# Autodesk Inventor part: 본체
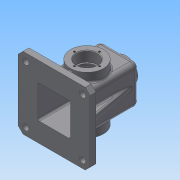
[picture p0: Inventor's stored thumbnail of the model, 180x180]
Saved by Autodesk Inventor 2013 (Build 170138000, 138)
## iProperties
Created: 2018-10
Part Number: 본체
Material: 일반
Document SubType Name: Modeling
Designer: Administrator
Density: 1 g/cm^3
Author: Administrator
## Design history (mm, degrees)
sketch "스케치1"
  geometry: L1 (32.5, -32.5)-(-32.5, -32.5); L2 (-32.5, -32.5)-(-32.5, 32.5); L3 (-32.5, 32.5)-(32.5, 32.5); L4 (32.5, 32.5)-(32.5, -32.5); L5 (32.5, -32.5)-(-32.5, 32.5); L6 (-32.5, -32.5)-(32.5, 32.5); 1 further point
  constraints: 12 end point, 2 midpoint, 2 parallel, 1 horizontal, 1 perpendicular
  dimensions: "d0" = 65 distance of L2.end L3.end; "d1" = 65 distance of L1.end L2.end
extrude "돌출1" new body sketch "스케치1" stored distance "d2" = 110; taper "d3" = 0 deg
sketch "스케치2"
  geometry: L1 (-27.5, 27.5)-(27.5, 27.5); L2 (27.5, 27.5)-(27.5, -27.5); L3 (27.5, -27.5)-(-27.5, -27.5); L4 (-27.5, -27.5)-(-27.5, 27.5); L5 (-27.5, 27.5)-(27.5, -27.5); L6 (27.5, 27.5)-(-27.5, -27.5); 1 further point
  constraints: 12 end point, 2 midpoint, 2 parallel, 1 horizontal, 1 perpendicular
  dimensions: "d4" = 55 distance of L2.end L3.end; "d5" = 55 distance of L1.end L2.end
extrude "돌출2" cut sketch "스케치2" distance "d6" = 105; taper "d7" = 0 deg
fillet "모깎기1" dims "d8" = 8
sketch "스케치3"
  geometry: L1 (57, 0)-(49, 0) reference; C1 r 27.5 at (24.5, 55); 1 further point
  constraints: 1 centre point, 1 coincident
  dimensions: "d9" = 55 diameter of C1; "d10" = 55 distance from line of L1 C1.centre
extrude "돌출3" join sketch "스케치3" distance "d11" = 15; taper "d12" = 0 deg
sketch "스케치4"
  geometry: C1 r 27.5 at (0, 0) reference; 1 further point
  constraints: 1 coincident
hole "구멍1" sketch "스케치4" at (0, 0) diameter "d13" = 30; stored, may be unused: countersink angle "d17" = 90 deg, drill point angle "d19" = 0 deg; dims "d14" = 6, "d15" = 35, "d16" = 17, "d18" = 20
sketch "스케치5"
  geometry: C1 r 17.5 at (0, 0) reference; 1 further point
  constraints: 1 vertical alignment
  dimensions: "d20" = 21 distance of C1.centre point (0, 21)
hole "구멍2" sketch "스케치5" at (0, 21) diameter "d21" = 3.242; stored, may be unused: countersink angle "d25" = 90 deg, drill point angle "d27" = 118 deg; dims "d22" = 8, "d23" = 35, "d24" = 17, "d26" = 10
chamfer "모따기1" distance "d31" = 1; stored, may be unused: second distance "d32" = 2, angle "d33" = 45 deg
fillet "모깎기2" dims "d34" = 0.3
fillet "모깎기3" dims "d35" = 3
chamfer "모따기2" distance "d36" = 1; stored, may be unused: second distance "d37" = 2, angle "d38" = 45 deg
fillet "모깎기4" dims "d39" = 0.3
fillet "모깎기5" dims "d40" = 3
node "작업 평면1"
sketch "스케치6"
  geometry: C1 r 20 at (0, 0); 1 further point
  constraints: 1 centre point, 1 coincident
  dimensions: "d42" = 40 diameter of C1
extrude "돌출4" join sketch "스케치6" stored distance "d43" = 15; taper "d44" = 7 deg
sketch "스케치7"
  geometry: C1 r 20 at (0, 0) reference; 1 further point
  constraints: 1 coincident
hole "구멍3" sketch "스케치7" at (0, 0) diameter "d45" = 22.835; stored, may be unused: countersink angle "d49" = 90 deg, drill point angle "d51" = 118 deg; dims "d46" = 8, "d47" = 35, "d48" = 17, "d50" = 10
chamfer "모따기3" distance "d52" = 1; stored, may be unused: second distance "d53" = 2, angle "d54" = 45 deg
fillet "모깎기6" dims "d55" = 3
fillet "모깎기7" dims "d56" = 3
fillet "모깎기8" dims "d57" = 3
sketch "스케치8"
  geometry: L1 (-24.5, -32.5)-(24.5, -32.5) reference; L2 (32.5, -24.5)-(32.5, 24.5) reference; L3 (24.5, 32.5)-(-24.5, 32.5) reference; L4 (-32.5, 24.5)-(-32.5, -24.5) reference; L5 (60, 60)-(-60, 60); L6 (-60, 60)-(-60, -60); L7 (-60, -60)-(60, -60); L8 (60, -60)-(60, 60); L9 (60, 60)-(-60, -60); L10 (-60, 60)-(60, -60); A1 r 8 centre (24.5, -24.5) between (24.5, -32.5) and (32.5, -24.5) reference; A2 r 8 centre (24.5, 24.5) between (32.5, 24.5) and (24.5, 32.5) reference; A3 r 8 centre (-24.5, 24.5) between (-24.5, 32.5) and (-32.5, 24.5) reference; A4 r 8 centre (-24.5, -24.5) between (-32.5, -24.5) and (-24.5, -32.5) reference; 1 further point
  constraints: 12 end point, 2 midpoint, 2 parallel, 1 horizontal, 1 perpendicular
  dimensions: "d58" = 120 distance of L7.end L6.end; "d59" = 120 distance of L6.end L5.end
extrude "돌출5" join sketch "스케치8" distance "d60" = 10; taper "d61" = 0 deg
chamfer "모따기4" distance "d62" = 8; stored, may be unused: second distance "d63" = 2, angle "d64" = 45 deg
sketch "스케치9"
  geometry: L1 (-47.5, 47.5)-(47.5, 47.5); L2 (47.5, 47.5)-(47.5, -47.5); L3 (47.5, -47.5)-(-47.5, -47.5); L4 (-47.5, -47.5)-(-47.5, 47.5); L5 (-47.5, 47.5)-(47.5, -47.5); L6 (47.5, 47.5)-(-47.5, -47.5); 7 further points
  constraints: 12 end point, 5 coincident, 3 midpoint, 2 parallel, 1 horizontal, 1 perpendicular
  dimensions: "d65" = 95 distance of L2.end L3.end; "d66" = 95 distance of L1.end L2.end
hole "구멍4" sketch "스케치9" at (-47.5, 47.5), (47.5, 47.5), (-47.5, -47.5), (47.5, -47.5) diameter "d67" = 10; stored, may be unused: countersink angle "d71" = 90 deg, drill point angle "d73" = 118 deg; dims "d68" = 8, "d69" = 35, "d70" = 17, "d72" = 10
sketch "스케치10"
  geometry: L1 (-12.418, 65)-(-11.418, 64) reference; L2 (-11.418, 64)-(-11.418, 50) reference; L3 (-11.418, 50)-(-24.5, 50) reference; L4 (-27.5, 47)-(-27.5, -55) reference; L5 (-27.5, -55)-(-60, -55) reference; L6 (-60, -55)-(-60, -45) reference; L7 (-60, -45)-(-32.5, -45) reference; L8 (-32.5, -45)-(-32.5, 47) reference; L9 (-24.5, 55)-(-23.882, 55) reference; L10 (-20.904, 57.634)-(-20, 65) reference; L11 (-20, 65)-(-12.418, 65) reference; L12 (11.418, 64)-(12.418, 65) reference; L13 (12.418, 65)-(20, 65) reference; L14 (20, 65)-(20.904, 57.634) reference; L15 (23.882, 55)-(24.5, 55) reference; L16 (32.5, 47)-(32.5, -45) reference; L17 (32.5, -45)-(60, -45) reference; L18 (60, -45)-(60, -55) reference; L19 (60, -55)-(27.5, -55) reference; L20 (27.5, -55)-(27.5, 47) reference; L21 (24.5, 50)-(11.418, 50) reference; L22 (11.418, 50)-(11.418, 64) reference; L23 (-48, -45)-(-41.054, -5.608); L24 (-48, -45)-(-8, -45); A1 r 3 centre (-24.5, 47) between (-24.5, 50) and (-27.5, 47) reference; A2 r 8 centre (-24.5, 47) between (-24.5, 55) and (-32.5, 47) reference; A3 r 3 centre (-23.882, 58) between (-23.882, 55) and (-20.904, 57.634) reference; A4 r 3 centre (23.882, 58) between (20.904, 57.634) and (23.882, 55) reference; A5 r 8 centre (24.5, 47) between (32.5, 47) and (24.5, 55) reference; A6 r 3 centre (24.5, 47) between (27.5, 47) and (24.5, 50) reference; 1 further point
  constraints: 4 end point, 1 equal length, 1 horizontal, 1 point on line
  dimensions: "d74" = 40 distance of L23.start L23.end; "d75" = 80 deg angle of L24 L23; "d76" = 12 distance of L6.end L23.start
feature "리브1" sketch "스케치10" dims "d77" = 1, "d78" = 10, "d79" = 0, "d80" = 0, "d81" = 1, "d82" = 1
sketch "스케치11"
  geometry: L1 (-21, -36.526)-(-22.621, -37.5) reference; L2 (-22.621, -37.5)-(-22.621, -47.5) reference; L3 (-22.621, -47.5)-(-27.5, -47.5) reference; L4 (-27.5, -47.5)-(-27.5, -35.5) reference; L5 (-30.5, -32.5)-(-45, -32.5) reference; L6 (-45, -32.5)-(-45, -60) reference; L7 (-45, -60)-(-55, -60) reference; L8 (-55, -60)-(-55, -27.5) reference; L9 (-55, -27.5)-(-15, -27.5) reference; L10 (-15, -27.5)-(-15, -30.5) reference; L11 (-15, -30.5)-(-17.2, -30.5) reference; L12 (-17.5, -30.8)-(-17.5, -46.5) reference; L13 (-17.5, -46.5)-(-18.5, -47.5) reference; L14 (-18.5, -47.5)-(-19.379, -47.5) reference; L15 (-19.379, -47.5)-(-19.379, -37.5) reference; L16 (-19.379, -37.5)-(-21, -36.526) reference; L17 (22.621, -37.5)-(21, -36.526) reference; L18 (21, -36.526)-(19.379, -37.5) reference; L19 (19.379, -37.5)-(19.379, -47.5) reference; L20 (19.379, -47.5)-(18.5, -47.5) reference; L21 (18.5, -47.5)-(17.5, -46.5) reference; L22 (17.5, -46.5)-(17.5, -30.8) reference; L23 (17.2, -30.5)-(15, -30.5) reference; L24 (15, -30.5)-(15, -27.5) reference; L25 (15, -27.5)-(47, -27.5) reference; L26 (50, -24.5)-(50, -11.418) reference; L27 (50, -11.418)-(64, -11.418) reference; L28 (64, -11.418)-(65, -12.418) reference; L29 (65, -12.418)-(65, -20) reference; L30 (65, -20)-(57.634, -20.904) reference; L31 (55, -23.882)-(55, -24.5) reference; L32 (47, -32.5)-(30.5, -32.5) reference; L33 (27.5, -35.5)-(27.5, -47.5) reference; L34 (27.5, -47.5)-(22.621, -47.5) reference; L35 (22.621, -47.5)-(22.621, -37.5) reference; L36 (-22.621, 37.5)-(-21, 36.526) reference; L37 (-21, 36.526)-(-19.379, 37.5) reference; L38 (-19.379, 37.5)-(-19.379, 47.5) reference; L39 (-19.379, 47.5)-(-18.5, 47.5) reference; L40 (-18.5, 47.5)-(-17.5, 46.5) reference; L41 (-17.5, 46.5)-(-17.5, 30.8) reference; L42 (-17.2, 30.5)-(-15, 30.5) reference; L43 (-15, 30.5)-(-15, 27.5) reference; L44 (-15, 27.5)-(-55, 27.5) reference; L45 (-55, 27.5)-(-55, 60) reference; L46 (-55, 60)-(-45, 60) reference; L47 (-45, 60)-(-45, 32.5) reference; L48 (-45, 32.5)-(-30.5, 32.5) reference; L49 (-27.5, 35.5)-(-27.5, 47.5) reference; L50 (-27.5, 47.5)-(-22.621, 47.5) reference; L51 (-22.621, 47.5)-(-22.621, 37.5) reference; L52 (21, 36.526)-(22.621, 37.5) reference; L53 (22.621, 37.5)-(22.621, 47.5) reference; L54 (22.621, 47.5)-(27.5, 47.5) reference; L55 (27.5, 47.5)-(27.5, 35.5) reference; L56 (30.5, 32.5)-(47, 32.5) reference; L57 (55, 24.5)-(55, 23.882) reference; L58 (57.634, 20.904)-(65, 20) reference; L59 (65, 20)-(65, 12.418) reference; L60 (65, 12.418)-(64, 11.418) reference; L61 (64, 11.418)-(50, 11.418) reference; L62 (50, 11.418)-(50, 24.5) reference; L63 (47, 27.5)-(15, 27.5) reference; L64 (15, 27.5)-(15, 30.5) reference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; A1 r 3 centre (-30.5, -35.5) between (-27.5, -35.5) and (-30.5, -32.5) reference; A2 r 0.3 centre (-17.2, -30.8) between (-17.2, -30.5) and (-17.5, -30.8) reference; A3 r 0.3 centre (17.2, -30.8) between (17.5, -30.8) and (17.2, -30.5) reference; A4 r 3 centre (47, -24.5) between (47, -27.5) and (50, -24.5) reference; A5 r 3 centre (58, -23.882) between (57.634, -20.904) and (55, -23.882) reference; A6 r 8 centre (47, -24.5) between (47, -32.5) and (55, -24.5) reference; A7 r 3 centre (30.5, -35.5) between (30.5, -32.5) and (27.5, -35.5) reference; A8 r 0.3 centre (-17.2, 30.8) between (-17.5, 30.8) and (-17.2, 30.5) reference; A9 r 3 centre (-30.5, 35.5) between (-30.5, 32.5) and (-27.5, 35.5) reference; A10 r 3 centre (30.5, 35.5) between (27.5, 35.5) and (30.5, 32.5) reference; A11 r 8 centre (47, 24.5) between (55, 24.5) and (47, 32.5) reference; A12 r 3 centre (58, 23.882) between (55, 23.882) and (57.634, 20.904) reference; A13 r 3 centre (47, 24.5) between (50, 24.5) and (47, 27.5) reference; A14 r 0.3 centre (17.2, 30.8) between (17.2, 30.5) and (17.5, 30.8) reference; 1 further point
  constraints: 2 end point, 1 perpendicular, 1 point on line
  dimensions: "d83" = 15 distance from line of L72.start L44
feature "리브2" sketch "스케치11" dims "d84" = 1, "d85" = 6, "d86" = 0, "d87" = 0, "d88" = 1, "d89" = 1
fillet "모깎기9" dims "d90" = 3
fillet "모깎기10" dims "d91" = 3
fillet "모깎기11" dims "d92" = 1
sketch "스케치12"
  geometry: L1 (-8, 0)-(-8, -91) reference; L2 (4.5, 18)-(44.5, 18) reference; 1 further point
  constraints: 1 other
  dimensions: "d93" = 32.5 distance from line of L1 point (24.5, -8); "d94" = 26 distance from line of L2 point (24.5, -8)
feature "엠보싱1" sketch "스케치12" dims "d4" = 55, "d40" = 3, "d46" = 8, "d94" = 26, "d95" = 0.5, "d96" = 0
node "솔리드1"
pattern_circular "원형 패턴1" dims angle "d29" = 360 deg
mirror "대칭1"
mirror "대칭2"
mirror "대칭3"
node "절단 모서리 투영1"
node "절단 모서리 투영2"
